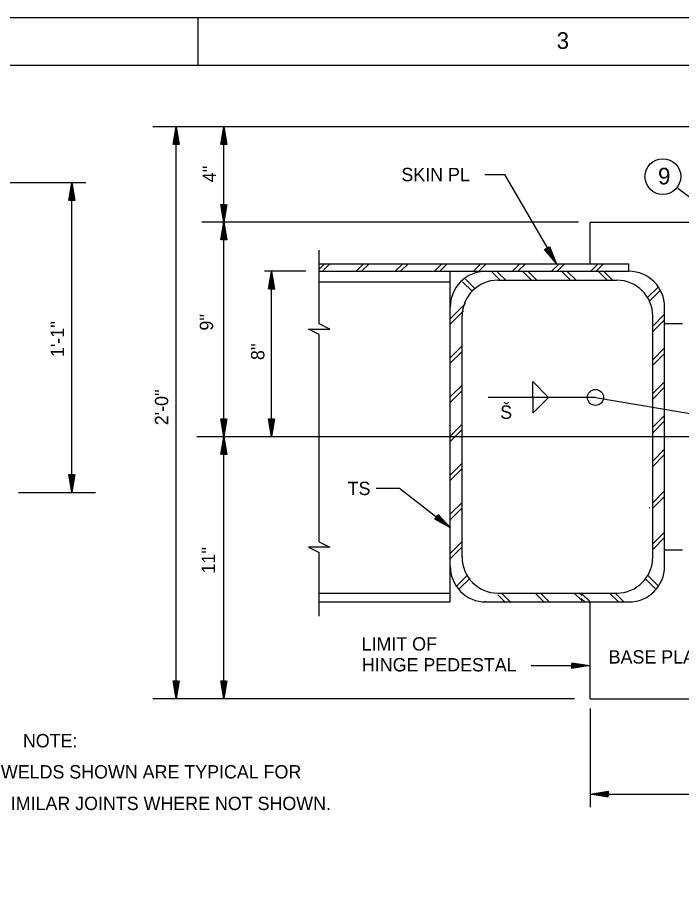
# Model space of a CAD drawing. Extents: x -0.2 to 13.5, y -0.2 to 9.5.
# Drawn here: x 4.91 to 7.233, y 6.294 to 9.333 of the extents above; entities that cross this region are included whole.
import ezdxf

# ---------------------------------------------------------------- set-up
doc = ezdxf.new("R2010")
doc.units = 0
for name, color, linetype in [('Level 0', 7, 'Continuous'), ('Level 1', 7, 'Continuous'), ('Level 13', 7, 'Continuous'), ('Level 2', 7, 'Continuous'), ('Level 3', 7, 'Continuous'), ('Level 4', 7, 'Continuous')]:
    doc.layers.add(name, color=color, linetype=linetype)

msp = doc.modelspace()

# ---------------------------------------------------------------- linework, layer by layer
at = {"layer": 'Level 0'}
for p, q in [((5.965, 8.4527), (5.9838, 8.4715)), ((5.9766, 8.4454), (6.0026, 8.4715)), ((6.0945, 8.4454), (6.1205, 8.4715)), ((6.1133, 8.4454), (6.1394, 8.4715)), ((6.2312, 8.4454), (6.2572, 8.4715)), ((6.25, 8.4454), (6.2761, 8.4715)), ((6.3679, 8.4454), (6.3939, 8.4715)), ((6.3867, 8.4454), (6.4128, 8.4715)), ((6.5046, 8.4454), (6.5306, 8.4715)), ((6.5234, 8.4454), (6.5495, 8.4715)), ((6.6413, 8.4454), (6.6673, 8.4715)), ((6.6601, 8.4454), (6.6862, 8.4715)), ((6.778, 8.4454), (6.804, 8.4715)), ((6.7969, 8.4454), (6.8229, 8.4715)), ((6.9147, 8.4454), (6.9407, 8.4715)), ((6.9336, 8.4454), (6.9596, 8.4715))]:
    msp.add_line(p, q, dxfattribs=at)
at = {"layer": 'Level 1'}
msp.add_line((5.5417, 9.1667), (5.5417, 9.3333), dxfattribs=at)
for points in [[(0, 9.3333), (13.3333, 9.3333), (13.3333, 0), (0, 0)], [(0.5, 9.1667), (13.1667, 9.1667), (13.1667, 0.1667), (0.5, 0.1667)]]:
    msp.add_lwpolyline(points, close=True, dxfattribs=at)
at = {"layer": 'Level 13'}
for points in [[(5.965, 8.2245), (5.9275, 8.2432), (6.0024, 8.2432), (5.965, 8.2619)], [(5.965, 7.4991), (6.0025, 7.4804), (5.9276, 7.4804), (5.965, 7.4617)]]:
    msp.add_lwpolyline(points, dxfattribs=at)
at = {"layer": 'Level 2'}
for p, q in [((5.465, 6.9506), (5.465, 8.9506)), ((5.6317, 8.6173), (5.6317, 8.9506)), ((5.6317, 7.8673), (5.6317, 8.6173)), ((6.9129, 8.6173), (8.5796, 8.6173)), ((6.9129, 8.4715), (6.9129, 8.6173)), ((5.965, 8.2619), (5.965, 8.5198)), ((5.965, 8.4715), (7.0483, 8.4715)), ((7.0483, 8.4454), (7.0483, 8.4715)), ((5.965, 8.4454), (7.0483, 8.4454)), ((6.4233, 7.2892), (6.4233, 8.4454)), ((6.5985, 8.4142), (6.5697, 8.443)), ((6.6174, 8.4141), (6.5886, 8.443)), ((6.7079, 8.4142), (6.6773, 8.4448)), ((6.7267, 8.4142), (6.6961, 8.4448)), ((6.8446, 8.4142), (6.814, 8.4448)), ((6.8634, 8.4142), (6.8328, 8.4448)), ((5.965, 8.409), (6.4233, 8.409)), ((6.5009, 8.3751), (6.4669, 8.4091)), ((6.5103, 8.3846), (6.4766, 8.4182)), ((6.59, 8.4142), (7.0067, 8.4142)), ((6.59, 8.4142), (6.59, 8.4142)), ((6.4233, 8.2794), (6.4763, 8.3324)), ((6.4233, 8.2605), (6.4696, 8.3068)), ((7.1733, 7.4142), (7.1733, 8.3204)), ((6.465, 7.4454), (6.465, 8.2892)), ((7.1317, 7.4454), (7.1317, 8.2892)), ((7.1733, 8.2631), (7.2358, 8.2631)), ((7.1733, 8.2631), (7.1733, 8.2631)), ((5.965, 7.4991), (5.965, 8.2245)), ((6.4233, 8.1427), (6.465, 8.1843)), ((6.4233, 8.1238), (6.465, 8.1655)), ((6.4233, 8.006), (6.465, 8.0476)), ((6.4233, 7.9871), (6.465, 8.0288)), ((6.4233, 7.8693), (6.465, 7.9109)), ((6.4233, 7.8504), (6.465, 7.8921)), ((5.537, 7.8673), (9.0726, 7.8673)), ((5.6317, 6.9506), (5.6317, 7.8673)), ((6.4233, 7.7325), (6.465, 7.7742)), ((6.4233, 7.7137), (6.465, 7.7554)), ((4.9135, 7.6724), (5.1833, 7.6724)), ((6.4233, 7.5958), (6.465, 7.6375)), ((6.4233, 7.577), (6.465, 7.6186)), ((7.1213, 7.6187), (7.1187, 7.6187)), ((6.4233, 7.4591), (6.465, 7.5008)), ((6.4233, 7.4403), (6.465, 7.4819)), ((5.965, 7.2394), (5.965, 7.4617)), ((7.1733, 7.4716), (7.2358, 7.4716)), ((6.4452, 7.3443), (6.4838, 7.3829)), ((6.4538, 7.334), (6.4927, 7.3729)), ((5.965, 7.3204), (6.4233, 7.3204)), ((6.4233, 7.3204), (6.4233, 7.3204)), ((6.59, 7.3204), (7.0067, 7.3204)), ((6.6166, 7.2873), (6.59, 7.3139)), ((6.6355, 7.2873), (6.6024, 7.3204)), ((6.7534, 7.2873), (6.7202, 7.3204)), ((6.7722, 7.2873), (6.7391, 7.3204)), ((6.8846, 7.2928), (6.8569, 7.3204)), ((6.8846, 7.3117), (6.8758, 7.3204)), ((5.965, 7.2892), (6.4233, 7.2892)), ((6.4233, 7.2892), (6.4233, 7.2892)), ((6.5455, 7.289), (6.5481, 7.2916)), ((6.5483, 7.2892), (7.0483, 7.2892)), ((6.9129, 6.9506), (6.9129, 7.2892)), ((6.9129, 6.9506), (8.5796, 6.9506)), ((6.9129, 6.6173), (8.5796, 6.6173))]:
    msp.add_line(p, q, dxfattribs=at)
for points in [[(6.9719, 8.4142), (6.9407, 8.4454)], [(6.9908, 8.4142), (6.9595, 8.4454)], [(7.1139, 8.3535), (7.1514, 8.3911)], [(7.1204, 8.3412), (7.1586, 8.3794)], [(7.1317, 8.2535), (7.1733, 8.2952)], [(7.1317, 8.2346), (7.1733, 8.2763)], [(7.1317, 8.1356), (7.1733, 8.1773)], [(7.1317, 8.1168), (7.1733, 8.1585)], [(7.1317, 8.0178), (7.1733, 8.0595)], [(7.1317, 7.9989), (7.1733, 8.0406)], [(7.1317, 7.8999), (7.1733, 7.9416)], [(7.1317, 7.8811), (7.1733, 7.9228)], [(7.1317, 7.7821), (7.1733, 7.8238)], [(7.1317, 7.7632), (7.1733, 7.8049)], [(7.1317, 7.6357), (7.1733, 7.6774)], [(7.1317, 7.6168), (7.1733, 7.6585)], [(7.1317, 7.492), (7.1733, 7.5337)], [(7.1317, 7.4732), (7.1733, 7.5148)], [(7.1436, 7.3333), (7.1066, 7.3703)], [(7.1518, 7.344), (7.1142, 7.3816)], [(6.8943, 7.2892), (6.8817, 7.3018)], [(6.9132, 7.2892), (6.8819, 7.3204)], [(7.0122, 7.2892), (6.9809, 7.3204)], [(7.031, 7.2892), (6.9998, 7.3204)]]:
    msp.add_lwpolyline(points, dxfattribs=at)
for centre, start, end in [((6.5483, 8.3204), 90, 180), ((7.0483, 8.3204), 0, 90), ((6.59, 8.2892), 90, 180), ((7.0067, 8.2892), 0, 90), ((6.59, 7.4454), 180, 270), ((7.0067, 7.4454), 270, 0), ((6.5483, 7.4142), 180, 270), ((7.0483, 7.4142), 270, 0)]:
    msp.add_arc(centre, 0.125, start, end, dxfattribs=at)
at = {"layer": 'Level 3'}
for p, q in [((8.5265, 8.9506), (5.3836, 8.9506)), ((5.465, 8.9506), (5.465, 8.9506)), ((5.6317, 8.9506), (5.6317, 8.9506)), ((5.465, 8.9333), (5.465, 8.9333)), ((5.6317, 8.9333), (5.6317, 8.9333)), ((6.5444, 8.7839), (6.6127, 8.7839)), ((6.6127, 8.7839), (6.7934, 8.4735)), ((4.5364, 8.7558), (5.1492, 8.7558)), ((5.1003, 7.6724), (5.1003, 8.7558)), ((5.1003, 8.7558), (5.1003, 8.7558)), ((5.1003, 8.7384), (5.1003, 8.7384)), ((7.2199, 8.7362), (7.7934, 8.3039)), ((5.6317, 8.6346), (5.6317, 8.6346)), ((6.8719, 8.6173), (5.5551, 8.6173)), ((5.6317, 8.6173), (5.6317, 8.6173)), ((5.6317, 8.6173), (5.6317, 8.6173)), ((5.6317, 8.6), (5.6317, 8.6)), ((6.7847, 8.4885), (6.7847, 8.4885)), ((6.7934, 8.4735), (6.7934, 8.4735)), ((5.9182, 8.4454), (5.7743, 8.4454)), ((5.7983, 8.4454), (5.7983, 8.4454)), ((5.7983, 7.8673), (5.7983, 8.4454)), ((5.7983, 8.4281), (5.7983, 8.4281)), ((6.9314, 8.0045), (7.4073, 7.9236)), ((5.6317, 7.8846), (5.6317, 7.8846)), ((5.7983, 7.8846), (5.7983, 7.8846)), ((5.6317, 7.8673), (5.6317, 7.8673)), ((5.6317, 7.8673), (5.6317, 7.8673)), ((5.6317, 7.85), (5.6317, 7.85)), ((5.7983, 7.8673), (5.7983, 7.8673)), ((5.1003, 7.6898), (5.1003, 7.6898)), ((5.1003, 7.6724), (5.1003, 7.6724)), ((6.4112, 7.5595), (6.4112, 7.5595)), ((6.4249, 7.5489), (6.4249, 7.5489)), ((6.7066, 7.0666), (6.9116, 7.0666)), ((6.8943, 7.0666), (6.8943, 7.0666)), ((6.9116, 7.0666), (6.9116, 7.0666)), ((5.465, 6.968), (5.465, 6.968)), ((5.6317, 6.968), (5.6317, 6.968)), ((6.8583, 6.9506), (5.3836, 6.9506)), ((5.465, 6.9506), (5.465, 6.9506)), ((5.6317, 6.9506), (5.6317, 6.9506)), ((6.9129, 6.9172), (6.9129, 6.5719)), ((6.9129, 6.6173), (6.9129, 6.6173)), ((6.9303, 6.6173), (6.9303, 6.6173))]:
    msp.add_line(p, q, dxfattribs=at)
for points in [[(5.4547, 8.8883), (5.465, 8.9506), (5.4753, 8.8883), (5.4577, 8.8883), (5.465, 8.9333), (5.472, 8.891), (5.4607, 8.891), (5.465, 8.9166), (5.4687, 8.8936), (5.464, 8.8936), (5.465, 8.8993)], [(5.6213, 8.8883), (5.6317, 8.9506), (5.642, 8.8883), (5.6243, 8.8883), (5.6317, 8.9333), (5.6387, 8.891), (5.6273, 8.891), (5.6317, 8.9166), (5.6353, 8.8936), (5.6307, 8.8936), (5.6317, 8.8993)], [(5.0899, 8.6934), (5.1003, 8.7558), (5.1106, 8.6934), (5.0929, 8.6934), (5.1003, 8.7384), (5.1073, 8.6961), (5.0959, 8.6961), (5.1003, 8.7218), (5.1039, 8.6988), (5.0993, 8.6988), (5.1003, 8.7044)], [(5.642, 8.6796), (5.6317, 8.6173), (5.6213, 8.6796), (5.639, 8.6796), (5.6317, 8.6346), (5.6247, 8.677), (5.636, 8.677), (5.6317, 8.6513), (5.628, 8.6743), (5.6327, 8.6743), (5.6317, 8.6686)], [(5.6213, 8.555), (5.6317, 8.6173), (5.642, 8.555), (5.6243, 8.555), (5.6317, 8.6), (5.6387, 8.5576), (5.6273, 8.5576), (5.6317, 8.5833), (5.6353, 8.5603), (5.6307, 8.5603), (5.6317, 8.566)], [(6.771, 8.5326), (6.7934, 8.4735), (6.7531, 8.5222), (6.7684, 8.5311), (6.7847, 8.4885), (6.7574, 8.5215), (6.7672, 8.5273), (6.7763, 8.5029), (6.7616, 8.5209), (6.7656, 8.5233), (6.7676, 8.5179)], [(5.788, 8.3831), (5.7983, 8.4454), (5.8087, 8.3831), (5.791, 8.3831), (5.7983, 8.4281), (5.8053, 8.3858), (5.794, 8.3858), (5.7983, 8.4114), (5.802, 8.3884), (5.7973, 8.3884), (5.7983, 8.3941)], [(5.642, 7.9296), (5.6317, 7.8673), (5.6213, 7.9296), (5.639, 7.9296), (5.6317, 7.8846), (5.6247, 7.927), (5.636, 7.927), (5.6317, 7.9013), (5.628, 7.9243), (5.6327, 7.9243), (5.6317, 7.9186)], [(5.8087, 7.9296), (5.7983, 7.8673), (5.788, 7.9296), (5.8057, 7.9296), (5.7983, 7.8846), (5.7913, 7.927), (5.8027, 7.927), (5.7983, 7.9013), (5.7947, 7.9243), (5.7993, 7.9243), (5.7983, 7.9186)], [(5.6213, 7.805), (5.6317, 7.8673), (5.642, 7.805), (5.6243, 7.805), (5.6317, 7.85), (5.6387, 7.8076), (5.6273, 7.8076), (5.6317, 7.8333), (5.6353, 7.8103), (5.6307, 7.8103), (5.6317, 7.816)], [(5.1106, 7.7348), (5.1003, 7.6724), (5.0899, 7.7348), (5.1076, 7.7348), (5.1003, 7.6898), (5.0933, 7.7321), (5.1046, 7.7321), (5.1003, 7.7064), (5.0966, 7.7294), (5.1013, 7.7294), (5.1003, 7.7238)], [(6.1641, 7.6871), (6.2456, 7.6871), (6.4249, 7.5489)], [(6.3818, 7.5952), (6.4249, 7.5489), (6.3692, 7.5788), (6.38, 7.5928), (6.4112, 7.5595), (6.3733, 7.5798), (6.3803, 7.5888), (6.3979, 7.5697), (6.3775, 7.5808), (6.3803, 7.5845), (6.3842, 7.5803)], [(6.8493, 7.0769), (6.9116, 7.0666), (6.8493, 7.0562), (6.8493, 7.0739), (6.8943, 7.0666), (6.852, 7.0596), (6.852, 7.0709), (6.8776, 7.0666), (6.8546, 7.0629), (6.8546, 7.0676), (6.8603, 7.0666)], [(5.4753, 7.013), (5.465, 6.9506), (5.4547, 7.013), (5.4723, 7.013), (5.465, 6.968), (5.458, 7.0103), (5.4693, 7.0103), (5.465, 6.9846), (5.4613, 7.0076), (5.466, 7.0076), (5.465, 7.002)], [(5.642, 7.013), (5.6317, 6.9506), (5.6213, 7.013), (5.639, 7.013), (5.6317, 6.968), (5.6247, 7.0103), (5.636, 7.0103), (5.6317, 6.9846), (5.628, 7.0076), (5.6327, 7.0076), (5.6317, 7.002)], [(6.9753, 6.607), (6.9129, 6.6173), (6.9753, 6.6276), (6.9753, 6.61), (6.9303, 6.6173), (6.9726, 6.6243), (6.9726, 6.613), (6.9469, 6.6173), (6.9699, 6.621), (6.9699, 6.6163), (6.9643, 6.6173)]]:
    msp.add_lwpolyline(points, dxfattribs=at)
msp.add_circle((7.1671, 8.7767), 0.0625, dxfattribs=at)
at = {"layer": 'Level 4'}
for p, q in [((6.7118, 8.0602), (6.7676, 8.0043)), ((6.7118, 8.0039), (6.7118, 8.0602)), ((6.9314, 8.0045), (6.5563, 8.0045)), ((6.7118, 8.0051), (6.7118, 7.9489)), ((6.7118, 7.9489), (6.7676, 8.0047))]:
    msp.add_line(p, q, dxfattribs=at)
msp.add_circle((6.9314, 8.0045), 0.0281, dxfattribs=at)

# ---------------------------------------------------------------- texts
at = {"layer": 'Level 1'}
msp.add_text('3', height=0.0584, dxfattribs=at).set_placement((6.7956, 9.2231))
at = {"layer": 'Level 3'}
for s, p in [("4''", (5.6043, 8.7567)), ("1'-1''", (5.0726, 8.1456)), ("9''", (5.5941, 8.2381)), ("8''", (5.7734, 8.1351)), ("2'-0''", (5.4372, 7.9072)), ("11''", (5.6009, 7.3887))]:
    msp.add_text(s, height=0.04667, rotation=90, dxfattribs=at).set_placement(p)
for s, height, p in [('SKIN PL', 0.04667, (6.2526, 8.7605)), ('9', 0.0583, (7.1502, 8.7492)), ('Š', 0.0467, (6.5982, 7.9296)), ('TS', 0.04667, (6.0646, 7.663)), ('LIMIT OF', 0.04667, (6.1135, 7.1194)), ('BASE PLATE, MK', 0.046667, (6.9776, 7.0738)), ('HINGE PEDESTAL', 0.046667, (6.1146, 7.0464)), ('NOTE:', 0.04667, (4.9289, 6.7809)), ('WELDS SHOWN ARE TYPICAL FOR', 0.046667, (4.8519, 6.672)), ('SIMILAR JOINTS WHERE NOT SHOWN.', 0.046667, (4.8448, 6.5616))]:
    msp.add_text(s, height=height, dxfattribs=at).set_placement(p)

doc.saveas('drawing.dxf')
